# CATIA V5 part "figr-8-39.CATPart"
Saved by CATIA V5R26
Part number: Part2
Bounding box of the stored display mesh (mm): x -50 to 50, y -50 to 50, z 0 to 40
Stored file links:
  D:\_Deepak\CATIA\CATIA V5-6R2016_Deepak\Resources\Part files\Partfiles\c08_catia_v5_6r2016_prt\figr-8-39.CATPart
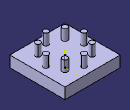
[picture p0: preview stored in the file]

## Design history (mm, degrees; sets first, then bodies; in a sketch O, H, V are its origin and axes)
Body1 (main body)
  Sketch1 on xy-plane, origin (0, 0, 0), H (1, 0, 0), V (0, 1, 0)
    line L1 (-50, 50) -> (50, 50)
    line L2 (50, 50) -> (50, -50)
    line L3 (50, -50) -> (-50, -50)
    line L4 (-50, -50) -> (-50, 50)
    axis line L5 (50, -50) -> (-50, 50)
    length L2 = 100
    length L3 = 100
    horizontal: L1 H, L3 H
    vertical: L2 V, L4 V
    midpoint: O L5
  Pad1: profile Sketch1, direction (0, 0, 1), length 20
  Sketch2 on face of Pad1, origin (0, 0, 20), H (1, 0, 0), V (0, 1, 0)
    circle A1 centre (0, -34.6458) radius 4.7511
    point P1 (0, -34.6458)
    coincidence: P1 V
  Pad2: profile Sketch2, direction (0, 0, 1), length 20
  CircPattern1: of Pad2, instances 8, angular step 45, axis from end face of Pad1
  Sketch3 on yz-plane, origin (0, 0, 0), H (0, 1, 0), V (0, 0, 1)
    line L1 (0, 0) -> (0, 20.0386)
    vertical: L1 V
